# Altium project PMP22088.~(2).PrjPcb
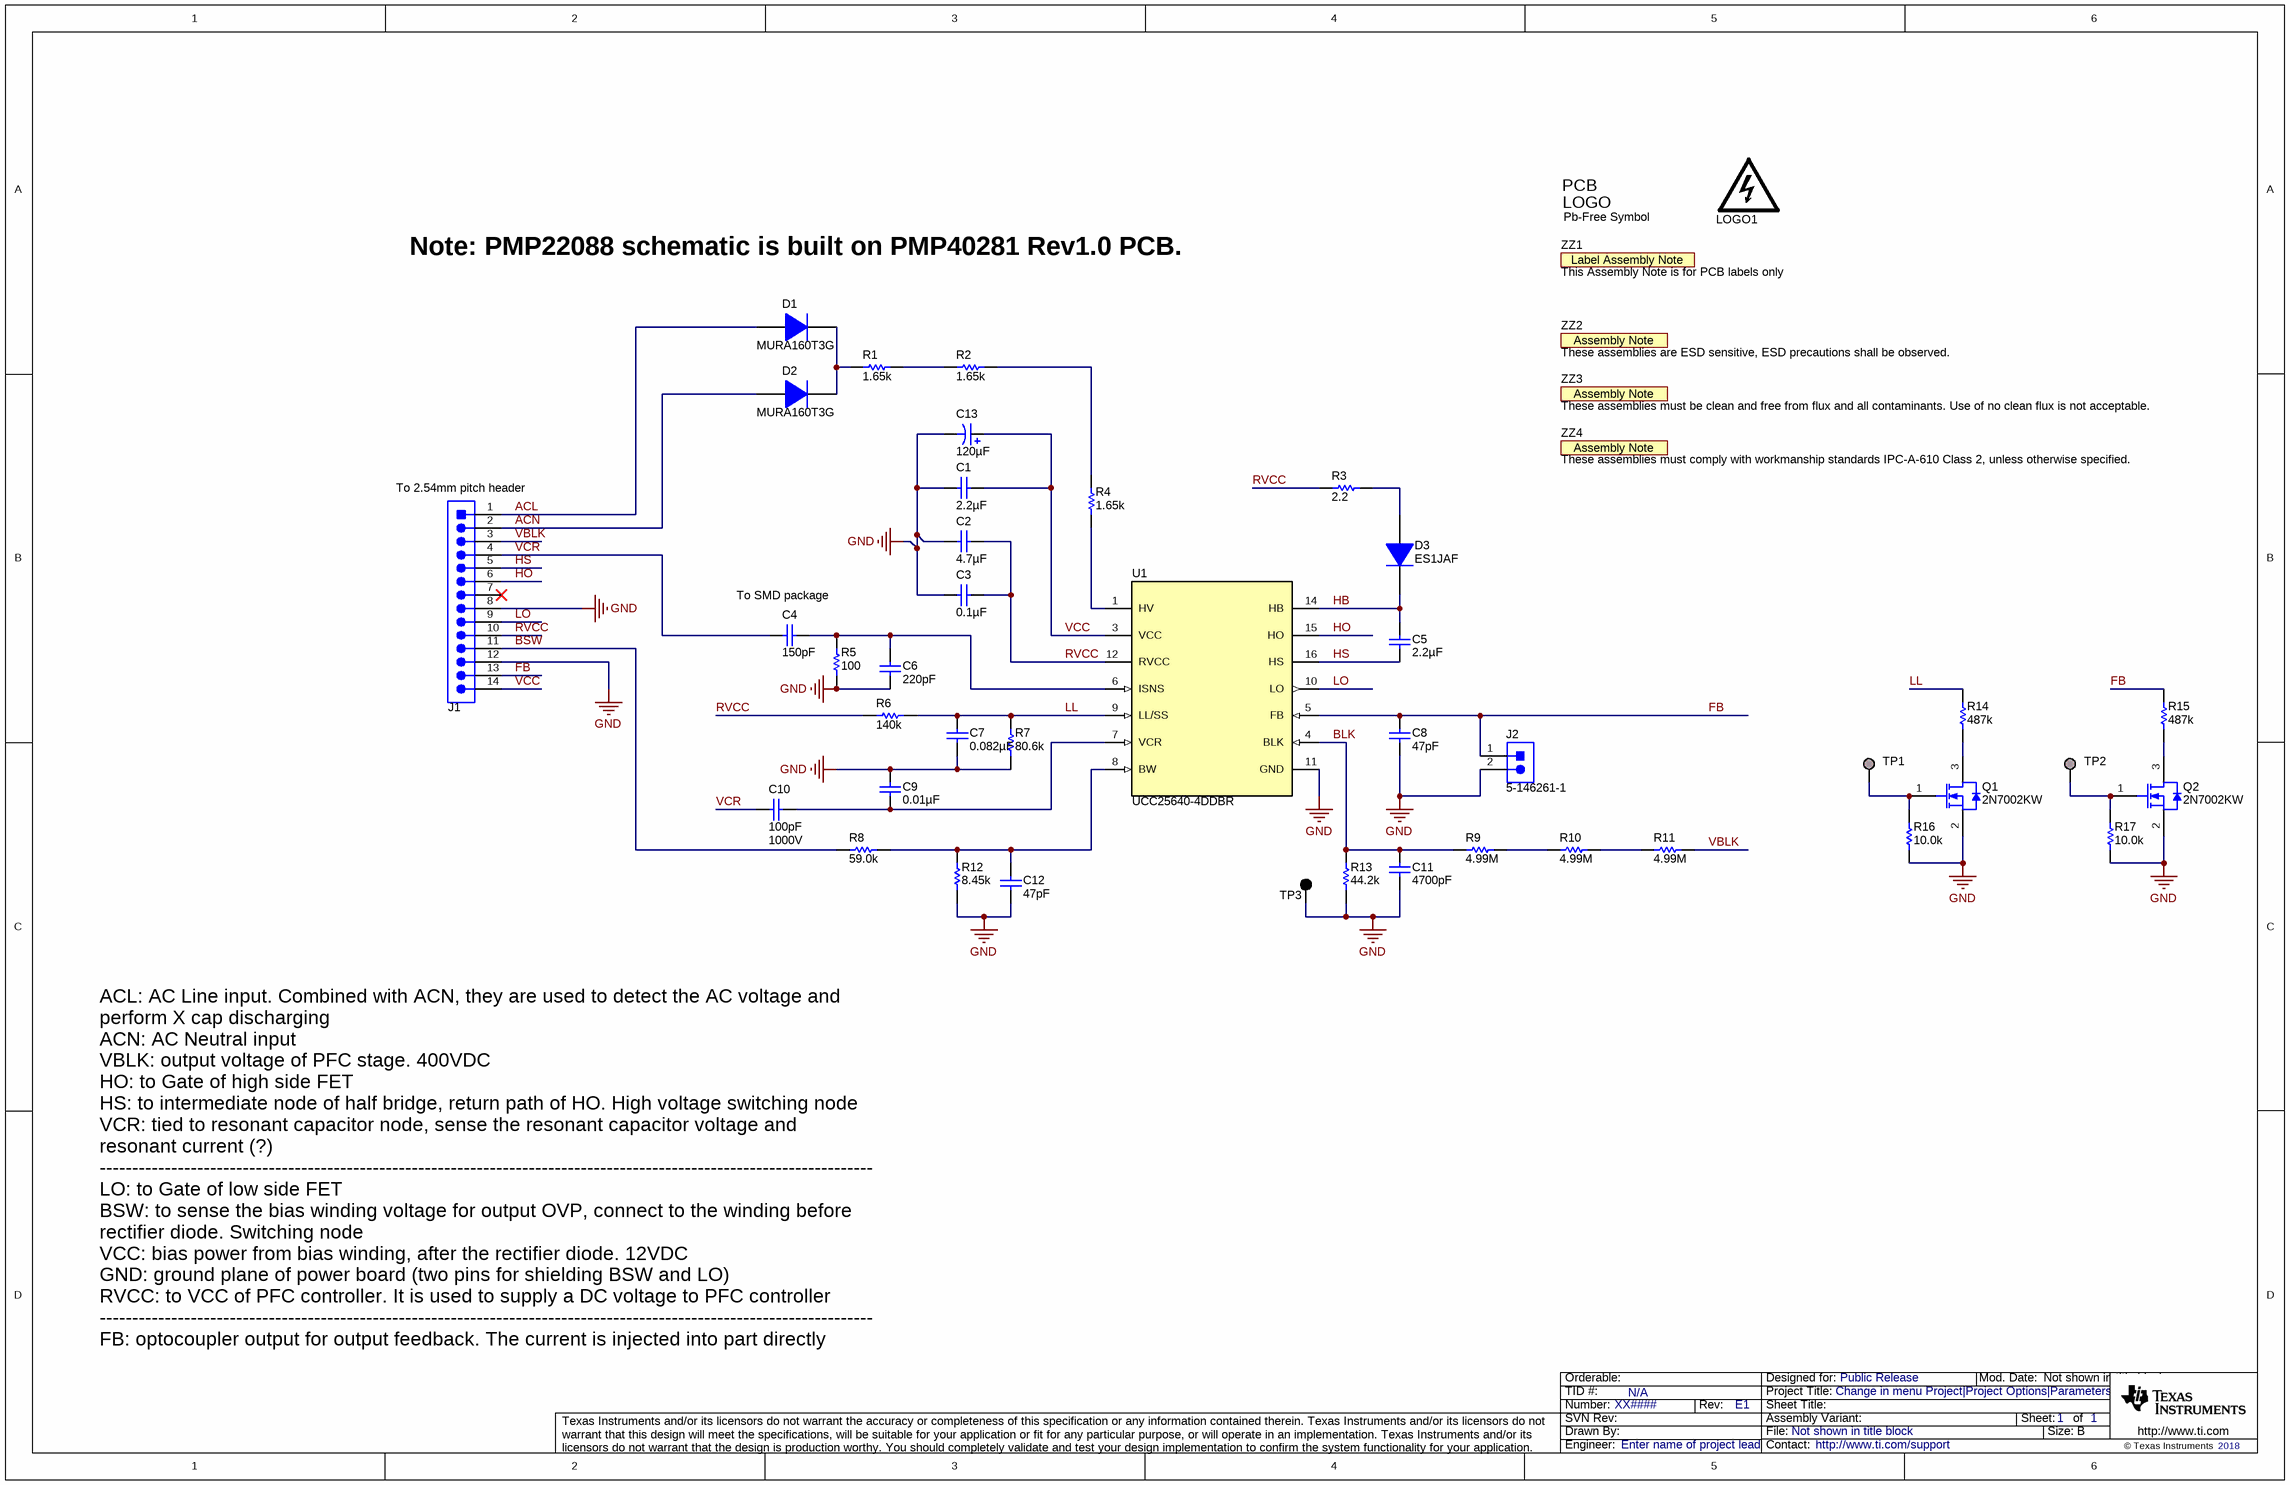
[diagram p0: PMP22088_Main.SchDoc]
CopyrightYear: 2018; PCB_Layout: Who did the Layout?; PCB_Rev: E1; PRJ_Customer: Public Release; PRJ_Engineer: Enter name of project lead; PRJ_Number: XX####; PRJ_Title: Change in menu Project|Project Options|Parameters; SCH_Rev: E1; TechSupport: http://www.ti.com/support; TID: N/A
1 sheet, 47 parts. Net scope: global (net labels, ports and power ports of the same name join across sheets).
Board file: PMP22088_PCB.PcbDoc

## Sheet PMP22088_Main.SchDoc
size 431 x 279 mm; Date: Not shown in title block; ApprovedBy: Not shown in title block; CheckedBy: Not shown in title block; Author: Not shown in title block; CompanyName: Not shown in title block; Engineer: Not shown in title block; Organization: Not shown in title block; Address1: Not shown in title block; Address2: Not shown in title block; Address3: Not shown in title block; Address4: Not shown in title block; DocumentNumber: 1; Revision: Use project parameter SCH_Rev; SheetNumber: 1; SheetTotal: 1; PageSetup: Record=PageOptions¦CenterHorizontal=True¦CenterVertical=True¦PrintScale=1.00¦XCorrection=1.00¦YCorrection=1.00¦PrintKind=0¦BorderSize=5000000¦LeftOffset=0¦BottomOffset=0¦Orientation=2¦PaperLength=1000¦PaperWidth=1000¦Scale=100¦PaperSource=15¦PrintQuality=600¦MediaType=1¦DitherType=10¦PaperKind=Letter¦PrintScaleMode=1

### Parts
C1  ValueDisplayed: 2.2µF  [0805_HV]  (hidden comment: C2012X7R1V225K085AC)
C2  ValueDisplayed: 4.7µF  [0603]  (hidden comment: GRM188Z71C475KE21D)
C3  ValueDisplayed: 0.1µF  [0402]  (hidden comment: GRM155R71C104KA88D)
C4  ValueDisplayed: 150pF  [1206]  (hidden comment: GRM31A5C2J151JW01D)
C5  ValueDisplayed: 2.2µF  [1206]  (hidden comment: C1206C225K4RACTU)
C6  ValueDisplayed: 220pF  [0603]  (hidden comment: C0603X221K5RACTU)
C7  ValueDisplayed: 0.082µF  [0603]  (hidden comment: GRM188R71E823KA01D)
C8  ValueDisplayed: 47pF  [0402]  (hidden comment: GRM1555C1H470FA01D)
C9  ValueDisplayed: 0.01µF  [0603]  (hidden comment: 06031C103KAT2A)
C10  ValueDisplayed: 100pF  Value2: 1000V  [1210]  (hidden comment: VJ1210A101JXGAT5Z)
C11  ValueDisplayed: 4700pF  [0603]  (hidden comment: 06031C472JAT2A)
C12  ValueDisplayed: 47pF  [0603]  (hidden comment: GRM1885C1H470FA01J)
C13  ValueDisplayed: 120µF  [ZLQ_630x1100]  (hidden comment: 35ZLQ120MEFC6.3X11)
D1  MURA160T3G  [SMA]
D2  MURA160T3G  [SMA]
D3  ES1JAF  [SMAF]
J1  4-644694-4  [TE_4-644694-4]  (value not drawn)
J2  5-146261-1  [CONN_5-146261-1]
LOGO1  DANGER HIGH VOLTAGE  [IEC_HighVoltage_Small]  (value not drawn)  (no BOM)
Logo2  Pb-Free Symbol  [Pb-Free_Overlay_Small]  (no BOM)
Q1  2N7002KW  [SOT-323]
Q2  2N7002KW  [SOT-323]
R1  ValueDisplayed: 1.65k  [1206]  (hidden comment: CRCW12061K65FKEA)
R2  ValueDisplayed: 1.65k  [1206]  (hidden comment: CRCW12061K65FKEA)
R3  ValueDisplayed: 2.2  [0603]  (hidden comment: CRCW06032R20JNEA)
R4  ValueDisplayed: 1.65k  [1206]  (hidden comment: CRCW12061K65FKEA)
R5  ValueDisplayed: 100  [0603]  (hidden comment: CRCW0603100RFKEA)
R6  ValueDisplayed: 140k  [0603]  (hidden comment: CRCW0603140KFKEA)
R7  ValueDisplayed: 80.6k  [0603]  (hidden comment: CRCW060380K6FKEA)
R8  ValueDisplayed: 59.0k  [0603]  (hidden comment: CRCW060359K0FKEA)
R9  ValueDisplayed: 4.99M  [1206]  (hidden comment: CRCW12064M99FKEA)
R10  ValueDisplayed: 4.99M  [1206]  (hidden comment: CRCW12064M99FKEA)
R11  ValueDisplayed: 4.99M  [1206]  (hidden comment: CRCW12064M99FKEA)
R12  ValueDisplayed: 8.45k  [0603]  (hidden comment: RC0603FR-078K45L)
R13  ValueDisplayed: 44.2k  [0603]  (hidden comment: CRCW060344K2FKEA)
R14  ValueDisplayed: 487k  [0402]  (hidden comment: CRCW0402487KFKED)
R15  ValueDisplayed: 487k  [0402]  (hidden comment: CRCW0402487KFKED)
R16  ValueDisplayed: 10.0k  [0402]  (hidden comment: CRCW040210K0FKED)
R17  ValueDisplayed: 10.0k  [0402]  (hidden comment: CRCW040210K0FKED)
TP1  TESTPOINT  [PAD_1MM_SQUARE]  (value not drawn)  (no BOM)
TP2  TESTPOINT  [PAD_1MM_SQUARE]  (value not drawn)  (no BOM)
TP3  5011  [Keystone5011]  (value not drawn)
U1  UCC25640-4DDBR  [DDB0014A]
ZZ1  This Assembly Note is for PCB labels only  [AssemblyNoteLabel]  (no BOM)
ZZ2  These assemblies are ESD sensitive, ESD precautions shall be observed.  [AssemblyNote]  (no BOM)
ZZ3  These assemblies must be clean and free from flux and all contaminants. Use of no clean flux is not acceptable.  [AssemblyNote]  (no BOM)
ZZ4  These assemblies must comply with workmanship standards IPC-A-610 Class 2, unless otherwise specified.  [AssemblyNote]  (no BOM)

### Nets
GND: C1.1 C2.1 C3.1 C6.2 C7.2 C8.2 C9.1 C11.2 C12.2 C13.2(-) J1.8 J1.12 J2.2 Q1.2(S) Q2.2(S) R5.1 R7.1 R12.1 R13.1 R16.1 R17.1 TP3.1 U1.11(GND)
ACL: D1.2(A) J1.1
ACN: D2.2(A) J1.2
BLK: C11.1 R9.1 R13.2 U1.4(BLK)
BSW: J1.11 R8.2
FB: C8.1 J1.13 J2.1 R15.2 U1.5(FB)
HB: C5.1 D3.1(K) U1.14(HB)
HO: J1.6 U1.15(HO)
HS: C5.2 J1.5 U1.16(HS)
LL: C7.1 R6.1 R7.2 R14.2 U1.9(LL/SS)
LO: J1.9 U1.10(LO)
RVCC: C2.2 C3.2 J1.10 R3.2 R6.2 U1.12(RVCC)
VBLK: J1.3 R11.2
VCC: C1.2 C13.1(+) J1.14 U1.3(VCC)
VCR: C4.1 C10.1 J1.4
NetC4_2: C4.2 C6.1 R5.2 U1.6(ISNS)
NetC9_2: C9.2 C10.2 U1.7(VCR)
NetC12_1: C12.1 R8.1 R12.2 U1.8(BW)
NetD1_1: D1.1(K) D2.1(K) R1.1
NetD3_2: D3.2(A) R3.1
NetQ1_1: Q1.1(G) R16.2 TP1.1
NetQ1_3: Q1.3(D) R14.1
NetQ2_1: Q2.1(G) R17.2 TP2.1
NetQ2_3: Q2.3(D) R15.1
NetR1_2: R1.2 R2.1
NetR2_2: R2.2 R4.2
NetR4_1: R4.1 U1.1(HV)
NetR9_2: R9.2 R10.1
NetR10_2: R10.2 R11.1

Not connected (* = marked no-connect by the designer): J1 7*

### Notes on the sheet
- Note: PMP22088 schematic is built on PMP40281 Rev1.0 PCB.
- (near J1) To 2.54mm pitch header
- To SMD package
- ACL: AC Line input. Combined with ACN, they are used to detect the AC voltage and perform X cap discharging
  ACN: AC Neutral input
  VBLK: output voltage of PFC stage. 400VDC
  HO: to Gate of high side FET
  HS: to intermediate node of half bridge, return path of HO. High voltage switching node
  VCR: tied to resonant capacitor node, sense the resonant capacitor voltage and resonant current (?)
  -----------------------------------------------------------------------------------------------------------------------
  LO: to Gate of low side FET
  BSW: to sense the bias winding voltage for output OVP, connect to the winding before rectifier diode. Switching node
  VCC: bias power from bias winding, after the rectifier diode. 12VDC
  GND: ground plane of power board (two pins for shielding BSW and LO)
  RVCC: to VCC of PFC controller. It is used to supply a DC voltage to PFC controller
  -----------------------------------------------------------------------------------------------------------------------
  FB: optocoupler output for output feedback. The current is injected into part directly

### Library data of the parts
C1 = C2012X7R1V225K085AC: CAP, CERM, 2.2 µF, 35 V, +/- 10%, X7R, 0805; Manufacturer: TDK; Polarized: N; CompType: Capacitor; Value: 2.2uF; U/M: EA; Cap_F: 0.0000022; Tolerance_%: 10; Value1: Unknown; VDC_V: 35; Value2: 35V; TaMin_C: -55; TaMax_C: 125; Cap_Case: 0805; SizeArea_mm2: 2.5; SizeAreaWB_mm2: 6.75; SizeX_mm: 2; SizeY_mm: 1.25; SizeZ_mm: 1.45; AEC Category: Q200
C2 = GRM188Z71C475KE21D: CAP, CERM, 4.7 µF, 16 V, +/- 10%, X7R, 0603; Manufacturer: MuRata; Polarized: N; CompType: Capacitor; Value: 4.7uF; U/M: EA; Cap_F: 0.0000047; Tolerance_%: 10; Value1: Unknown; VDC_V: 16; Value2: 16V; TaMin_C: -55; TaMax_C: 125; SizeArea_mm2: 1.28; SizeAreaWB_mm2: 4.68; SizeX_mm: 1.6; SizeY_mm: 0.8; SizeZ_mm: 1; AEC Category: Q200
C3 = GRM155R71C104KA88D: CAP, CERM, 0.1 µF, 16 V, +/- 10%, X7R, 0402; Manufacturer: MuRata; Polarized: N; CompType: Capacitor; Value: 0.1uF; U/M: EA; Cap_F: 0.0000001; Tolerance_%: 10; Value1: Unknown; VDC_V: 16; Value2: 16V; TaMin_C: -55; TaMax_C: 125; SizeArea_mm2: 0.5; SizeAreaWB_mm2: 3; SizeX_mm: 1; SizeZ_mm: 0.6; AEC Category: Q200
C4 = GRM31A5C2J151JW01D: CAP, CERM, 150 pF, 630 V, +/- 5%, C0G/NP0, 1206; Manufacturer: MuRata; Polarized: N; CompType: Capacitor; Value: 150pF; U/M: EA; Cap_F: 0.00000000015; Tolerance_%: 5; Value1: Unknown; VDC_V: 630; Value2: 630V; TaMin_C: -55; TaMax_C: 125; SizeAreaWB_mm2: 10.92; SizeArea_mm2: 5.12; SizeX_mm: 3.2; SizeY_mm: 1.6; SizeZ_mm: 1.35; AEC Category: Q200
C5 = C1206C225K4RACTU: CAP, CERM, 2.2 µF, 16 V, +/- 10%, X7R, 1206; Manufacturer: Kemet; Polarized: N; CompType: Capacitor; Value: 2.2uF; U/M: EA; Cap_F: 0.0000022; Tolerance_%: 10; ESR_ohm: 0.009; Value1: 0.009 ohm; VDC_V: 16; Value2: 16V; IRMS_A: 4.46; TaMin_C: -55; TaMax_C: 125; SizeArea_mm2: 5.12; SizeAreaWB_mm2: 10.92; SizeX_mm: 3.2; SizeY_mm: 1.6; SizeZ_mm: 1.35; AEC Category: Q200
C6 = C0603X221K5RACTU: CAP, CERM, 220 pF, 50 V,+/- 10%, X7R, 0603; Manufacturer: Kemet; Polarized: N; CompType: Capacitor; Value: 220pF; U/M: EA; Cap_F: 0.00000000022; Tolerance_%: 10; VDC_V: 50; Value2: 50V; TaMin_C: -55; TaMax_C: 125; SizeArea_mm2: 1.28; SizeAreaWB_mm2: 4.68; SizeX_mm: 1.6; SizeY_mm: 0.8; SizeZ_mm: 1; AEC Category: Q200; Green_Lifecycle: Not Set; Green_REACh: Incomplete
C7 = GRM188R71E823KA01D: CAP, CERM, 0.082 µF, 25 V,+/- 10%, X7R, 0603; Manufacturer: MuRata; Polarized: N; CompType: Capacitor; Value: 0.082uF; U/M: EA; Cap_F: 0.000000082; Tolerance_%: 10; VDC_V: 25; Value2: 25V; TaMin_C: -55; TaMax_C: 125; SizeArea_mm2: 1.28; SizeAreaWB_mm2: 4.68; SizeX_mm: 1.6; SizeY_mm: 0.8; SizeZ_mm: 1; AEC Category: Q200; Green_Lifecycle: Active; Green_REACh: Passed
C8 = GRM1555C1H470FA01D: CAP, CERM, 47 pF, 50 V, +/- 1%, C0G/NP0, 0402; Manufacturer: MuRata; Polarized: N; CompType: Capacitor; Value: 47pF; U/M: EA; Cap_F: 0.000000000047; Tolerance_%: 1; Value1: Unknown; VDC_V: 50; Value2: 50V; TaMin_C: -55; TaMax_C: 125; SizeArea_mm2: 0.5; SizeAreaWB_mm2: 3; SizeZ_mm: 0.6; AEC Category: Q200
C9 = 06031C103KAT2A: CAP, CERM, 0.01 µF, 100 V,+/- 10%, X7R, 0603; Manufacturer: AVX; Polarized: N; CompType: Capacitor; Value: 0.01uF; U/M: EA; Cap_F: 0.00000001; Tolerance_%: 10; ESR_ohm: 0.098; Value1: 0.098 ohm; VDC_V: 100; Value2: 100V; TaMin_C: -55; TaMax_C: 125; SizeArea_mm2: 1.28; SizeAreaWB_mm2: 4.68; SizeX_mm: 1.6; SizeY_mm: 0.8; SizeZ_mm: 1; AEC Category: Q200; Green_Lifecycle: Active; Green_REACh: Passed
C10 = VJ1210A101JXGAT5Z: CAP, CERM, 100 pF, 1000 V,+/- 5%, C0G/NP0, 1210; Manufacturer: Vishay-Vitramon; Polarized: N; CompType: Capacitor; Value: 100pF; U/M: EA; Cap_F: 0.0000000001; Tolerance_%: 5; VDC_V: 1000; TaMin_C: -55; TaMax_C: 125; SizeArea_mm2: 8; SizeAreaWB_mm2: 14.7; SizeX_mm: 3.2; SizeY_mm: 2.5; SizeZ_mm: 1.35; AEC Category: Q200
C11 = 06031C472JAT2A: CAP, CERM, 4700 pF, 100 V,+/- 5%, X7R, 0603; Manufacturer: AVX; Polarized: N; CompType: Capacitor; Value: 4700pF; U/M: EA; Cap_F: 0.0000000047; Tolerance_%: 5; ESR_ohm: 0.136; Value1: 0.136 ohm; VDC_V: 100; Value2: 100V; TaMin_C: -55; TaMax_C: 125; SizeArea_mm2: 1.28; SizeAreaWB_mm2: 4.68; SizeX_mm: 1.6; SizeY_mm: 0.8; SizeZ_mm: 1; AEC Category: Q200; Green_Lifecycle: Active; Green_REACh: Passed
C12 = GRM1885C1H470FA01J: CAP, CERM, 47 pF, 50 V,+/- 1%, C0G/NP0, 0603; Manufacturer: MuRata; Polarized: N; CompType: Capacitor; Value: 47pF; U/M: EA; Cap_F: 0.000000000047; Tolerance_%: 1; VDC_V: 50; Value2: 50V; TaMin_C: -55; TaMax_C: 125; SizeArea_mm2: 1.28; SizeAreaWB_mm2: 4.68; SizeX_mm: 1.6; SizeY_mm: 0.8; AEC Category: Q200; Green_Lifecycle: Not Set; Green_REACh: Incomplete
C13 = 35ZLQ120MEFC6.3X11: CAP, AL, 120 µF, 35 V, +/- 20%, TH; Manufacturer: Rubycon; Polarized: Y; CompType: Capacitor; Value: 120uF; U/M: EA; Cap_F: 0.00012; Tolerance_%: 20; Value1: Unknown; VDC_V: 35; Value2: 35V; IRMS_A: 0.62; TaMin_C: -40; TaMax_C: 105; Cap_Case: 6.3x11mm; SizeArea_mm2: 39.69; SizeAreaWB_mm2: 68.89; SizeX_mm: 6.3; SizeZ_mm: 12.5; AEC Category: Q200; AEC Qualified: N
D1 D2 = MURA160T3G: Diode, Ultrafast, 600 V, 1 A, AEC-Q101, SMA; Manufacturer: ON Semiconductor; U/M: EA; Vf_V: 1.05; Value: 600V; Value1: 1A; Value2: 1.05V; Io_A: 1; Vr_V: 600; TJmax_C: 175; SizeAreaWB_mm2: 37.3428; SizeArea_mm2: 16.3228; SizeX_mm: 5.59; SizeY_mm: 2.92; SizeZ_mm: 2.87; AEC Category: Q101; AEC Qualified: Y
D3 = ES1JAF: Diode, Ultrafast, 600 V, 1 A, AEC-Q101, SMAF; Manufacturer: Fairchild Semiconductor; U/M: EA; Vf_V: 1.7; Value: 600V; Value1: 1A; Value2: 1.7V; Io_A: 1; Vr_V: 600; TJmax_C: 150; SizeAreaWB_mm2: 19.95; SizeArea_mm2: 11.75; SizeX_mm: 4.7; SizeY_mm: 2.5; AEC Category: Q101; AEC Qualified: Y
J1 = 4-644694-4: Header, 100 mil, 14x1, Tin, R/A, TH; Manufacturer: TE Connectivity; SymbolCreator: a0411947; Pitch_mm: 2.54; Gender: Male; Shrouded: N; Row_Count: 1; Cert_CSA: Y
J2 = 5-146261-1: Header, 100mil, 2x1, Gold, TH; Manufacturer: TE Connectivity; SymbolCreator: a0412235
LOGO1 = IEC_HighVoltage: IEC 61010-1 High Voltage Warning; SymbolCreator: a0412235
Logo2 = Pb-Free: SymbolCreator: a0412235
Q1 Q2 = 2N7002KW: MOSFET, N-CH, 60 V, 0.31 A, SOT-323; Manufacturer: Fairchild Semiconductor; Alternate Manufacturer: None; U/M: EA; ChType: N; Value: 60V; VdsMax_V: 60; Value1: 1.6 ohm; Rdson45_ohm: 1.6; Value2: ? nC; Vgs_V: 2.1; IdsMax_A: 0.31; SizeAreaWB_mm2: 10.24; SizeArea_mm2: 4.84; SizeX_mm: 2.2; SizeZ_mm: 1.1; AEC Category: Q101
R1 R2 R4 = CRCW12061K65FKEA: RES, 1.65 k, 1%, 0.25 W, 1206; Manufacturer: Vishay-Dale; CompType: Resistor; Value: 1.65k; Res_ohm: 1650; Value_Code: 1k65; Tolerance_%: 1; Power_W: 0.25; Value2: 0.25W; VDC_V: 200; TempCo: 100 ppm/C; SizeArea_mm2: 5.12; SizeX_mm: 3.2; SizeY_mm: 1.6; SizeZ_mm: 1.35; EIA_Code: E96; U/M: EA; AEC Category: Q200
R3 = CRCW06032R20JNEA: RES, 2.2, 5%, 0.1 W, 0603; Manufacturer: Vishay-Dale; CompType: Resistor; Value: 2.2; Value_Code: 2R20; Tolerance_%: 5; Power_W: 0.1; Value2: 0.1W; VDC_V: 75; TempCo: 200 ppm/C; SizeArea_mm2: 1.28; SizeX_mm: 1.6; SizeY_mm: 0.8; SizeZ_mm: 1; EIA_Code: E24; U/M: EA; AEC Category: Q200
R5 = CRCW0603100RFKEA: RES, 100, 1%, 0.1 W, 0603; Manufacturer: Vishay-Dale; CompType: Resistor; Value: 100; Value_Code: 100R; Tolerance_%: 1; Power_W: 0.1; Value2: 0.1W; VDC_V: 75; TempCo: 100 ppm/C; SizeArea_mm2: 1.28; SizeX_mm: 1.6; SizeY_mm: 0.8; EIA_Code: E96; U/M: EA; AEC Category: Q200; Green_Lifecycle: Active; Green_REACh: Passed
R6 = CRCW0603140KFKEA: RES, 140 k, 1%, 0.1 W, 0603; Manufacturer: Vishay-Dale; CompType: Resistor; Value: 140k; Res_ohm: 140000; Tolerance_%: 1; Power_W: 0.1; Value2: 0.1W; VDC_V: 75; TempCo: 100 ppm/C; SizeArea_mm2: 1.28; SizeX_mm: 1.6; SizeY_mm: 0.8; EIA_Code: E96; U/M: EA; AEC Category: Q200; Green_Lifecycle: Active; Green_REACh: Passed
R7 = CRCW060380K6FKEA: RES, 80.6 k, 1%, 0.1 W, 0603; Manufacturer: Vishay-Dale; CompType: Resistor; Value: 80.6k; Res_ohm: 80600; Value_Code: 80k6; Tolerance_%: 1; Power_W: 0.1; Value2: 0.1W; VDC_V: 75; TempCo: 100 ppm/C; SizeArea_mm2: 1.28; SizeX_mm: 1.6; SizeY_mm: 0.8; EIA_Code: E96; U/M: EA; AEC Category: Q200; Green_Lifecycle: Active; Green_REACh: Passed
R8 = CRCW060359K0FKEA: RES, 59.0 k, 1%, 0.1 W, 0603; Manufacturer: Vishay-Dale; CompType: Resistor; Value: 59.0k; Res_ohm: 59000; Value_Code: 59k0; Tolerance_%: 1; Power_W: 0.1; Value2: 0.1W; VDC_V: 75; TempCo: 100 ppm/C; SizeArea_mm2: 1.28; SizeX_mm: 1.6; SizeY_mm: 0.8; EIA_Code: E96; U/M: EA; AEC Category: Q200; Green_Lifecycle: Active; Green_REACh: Passed
R9-R11 = CRCW12064M99FKEA: RES, 4.99 M, 1%, 0.25 W, 1206; Manufacturer: Vishay-Dale; CompType: Resistor; Value: 4.99Meg; Res_ohm: 4990000; Value_Code: 4M99; Tolerance_%: 1; Power_W: 0.25; Value2: 0.25W; VDC_V: 200; TempCo: 100 ppm/C; SizeArea_mm2: 5.12; SizeX_mm: 3.2; SizeY_mm: 1.6; SizeZ_mm: 1.35; EIA_Code: E96; U/M: EA; AEC Category: Q200
R12 = RC0603FR-078K45L: RES, 8.45 k, 1%, 0.1 W, 0603; Manufacturer: Yageo America; CompType: Resistor; Value: 8.45k; Res_ohm: 8450; Value_Code: 8k45; Tolerance_%: 1; Power_W: 0.1; Value2: 0.1W; VDC_V: 150; TempCo: 200 ppm/C; SizeArea_mm2: 1.28; SizeX_mm: 1.6; SizeY_mm: 0.8; EIA_Code: E96; U/M: EA; AEC Category: Q200; AEC Qualified: N; Green_Lifecycle: Active; Green_REACh: Passed
R13 = CRCW060344K2FKEA: RES, 44.2 k, 1%, 0.1 W, 0603; Manufacturer: Vishay-Dale; CompType: Resistor; Value: 44.2k; Res_ohm: 44200; Value_Code: 44k2; Tolerance_%: 1; Power_W: 0.1; Value2: 0.1W; VDC_V: 75; TempCo: 100 ppm/C; SizeArea_mm2: 1.28; SizeX_mm: 1.6; SizeY_mm: 0.8; EIA_Code: E96; U/M: EA; AEC Category: Q200; Green_Lifecycle: Active; Green_REACh: Passed
R14 R15 = CRCW0402487KFKED: RES, 487 k, 1%, 0.063 W, 0402; Manufacturer: Vishay-Dale; CompType: Resistor; Value: 487k; Res_ohm: 487000; Tolerance_%: 1; Power_W: 0.063; Value2: 0.063W; VDC_V: 50; TempCo: 100 ppm/C; SizeArea_mm2: 0.5; SizeZ_mm: 0.6; EIA_Code: E96; U/M: EA; AEC Category: Q200
R16 R17 = CRCW040210K0FKED: RES, 10.0 k, 1%, 0.063 W, 0402; Manufacturer: Vishay-Dale; CompType: Resistor; Value: 10.0k; Res_ohm: 10000; Value_Code: 10k0; Tolerance_%: 1; Power_W: 0.063; Value2: 0.063W; VDC_V: 50; TempCo: 100 ppm/C; SizeArea_mm2: 0.5; SizeZ_mm: 0.6; EIA_Code: E96; U/M: EA; AEC Category: Q200
TP1 TP2 = PAD_1MM_SQUARE: 1.0x1.0mm pad, square, SMD; Manufacturer: Any
TP3 = 5011: Test Point, Multipurpose, Black, TH; Manufacturer: Keystone; CompType: Test Point Loop; ContactFinish: Silver
U1 = UCC25630-1DDBR: Enhanced LLC Resonant Controller with Driver, DDB0014A (SOIC-14); Manufacturer: Texas Instruments; SymbolCreator: Altium; SizeArea_mm2: 59.4; SizeAreaWB_mm2: 95.2; SizeX_mm: 6; SizeY_mm: 9.9; SizeZ_mm: 1.75; CompType: IC; U/M: EA
ZZ1 = AssemblyNoteLabel: SymbolCreator: a0412235
ZZ2-ZZ4 = AssemblyNote: SymbolCreator: codlsc

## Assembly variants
001: not fitted FID1 FID2 FID3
